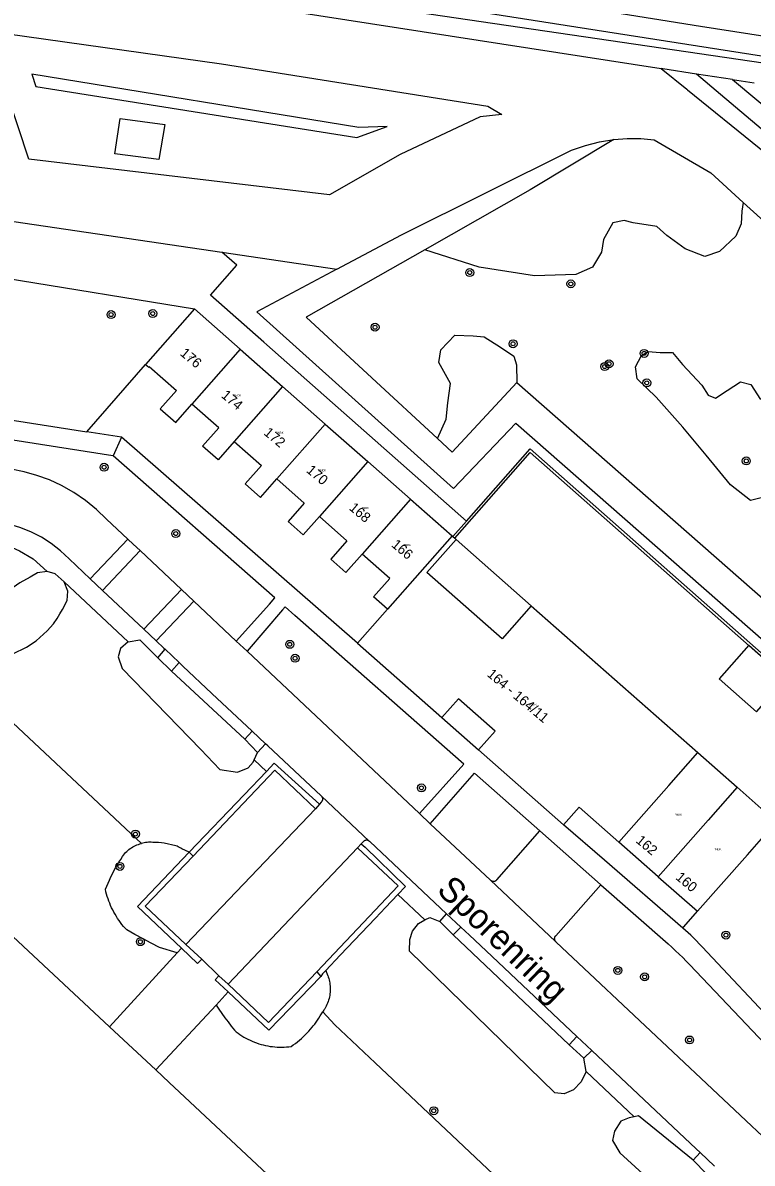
# Model space of a CAD drawing. Extents: x 132994 to 136000, y 393499 to 395512.
# Drawn here: x 133162.3 to 133235.6, y 394136.6 to 394251.1 of the extents above; entities that cross this region are included whole.
import ezdxf

# ---------------------------------------------------------------- set-up
doc = ezdxf.new("R2010")
doc.units = 0
for name, color, linetype in [('gg-anno-huisnummerreeks BGT', 7, 'Continuous'), ('gg-anno-openbare ruimte label', 7, 'Continuous'), ('gg-knt-bronhoudergrens niveau 01', 7, 'Continuous'), ('gg-kntw-bovenkant insteek waterloop', 7, 'Continuous'), ('gt-symb-boom', 7, 'Continuous'), ('gx-grn-maaiveld', 7, 'Continuous'), ('kenmerkpunt-x pandkandidaat', 7, 'Continuous')]:
    doc.layers.add(name, color=color, linetype=linetype)

# ---------------------------------------------------------------- blocks, each defined once
blk = doc.blocks.new('gt0-BOOM')
at = {"layer": 'gt-symb-boom'}
for radius in [0.4, 0.2]:
    blk.add_circle((0, 0), radius, dxfattribs=at)

msp = doc.modelspace()

# ---------------------------------------------------------------- linework, layer by layer
at = {"layer": 'gg-knt-bronhoudergrens niveau 01'}
msp.add_lwpolyline([(133235.24, 394188.61), (133232.26, 394185.23), (133236.01, 394181.93), (133238.99, 394185.3), (133235.24, 394188.61)], dxfattribs=at)
at = {"layer": 'gg-kntw-bovenkant insteek waterloop'}
msp.add_lwpolyline([(133000, 394279.68), (133030.54, 394275.9), (133128.46, 394261.71), (133226.43, 394246.51)], dxfattribs=at)
at = {"layer": 'gx-grn-maaiveld'}
for p, q in [((133226.6, 394246.48), (133226.43, 394246.51)), ((133229.99, 394245.96), (133226.6, 394246.48)), ((133233.58, 394245.41), (133229.99, 394245.96)), ((133233.58, 394245.41), (133235.77, 394245.07)), ((133234.68, 394233.07), (133242.31, 394226.14)), ((133161.43, 394231.16), (133182.33, 394228.07)), ((133182.33, 394228.07), (133193.87, 394226.36)), ((133160.66, 394225.47), (133179.57, 394222.38)), ((133179.57, 394222.38), (133174.66, 394216.8)), ((133179.57, 394222.38), (133184.17, 394218.33)), ((133184.17, 394218.33), (133179.31, 394212.82)), ((133184.17, 394218.33), (133188.42, 394214.59)), ((133168.77, 394210.04), (133174.66, 394216.8)), ((133188.42, 394214.59), (133183.56, 394209.08)), ((133188.42, 394214.59), (133192.69, 394210.82)), ((133158.67, 394211.61), (133168.77, 394210.04)), ((133192.69, 394210.82), (133187.84, 394205.31)), ((133192.69, 394210.82), (133196.97, 394207.05)), ((133172.24, 394209.5), (133168.77, 394210.04)), ((133172.24, 394209.5), (133171.41, 394207.63)), ((133196.97, 394207.05), (133192.12, 394201.54)), ((133196.97, 394207.05), (133201.26, 394203.27)), ((133201.26, 394203.27), (133196.41, 394197.76)), ((133201.26, 394203.27), (133205.43, 394199.59)), ((133205.51, 394199.52), (133206.88, 394201.08)), ((133205.43, 394199.59), (133198.95, 394192.24)), ((133205.51, 394199.52), (133205.43, 394199.59)), ((133205.51, 394199.52), (133205.7, 394199.36)), ((133205.7, 394199.36), (133205.83, 394199.24)), ((133172.88, 394199.27), (133169.1, 394195.29)), ((133213.39, 394192.58), (133205.83, 394199.24)), ((133174.1, 394198.12), (133170.33, 394194.13)), ((133174.1, 394198.12), (133178.26, 394194.21)), ((133166.48, 394195), (133172.92, 394188.96)), ((133170.33, 394194.13), (133169.1, 394195.29)), ((133174.48, 394190.22), (133170.33, 394194.13)), ((133178.26, 394194.21), (133174.48, 394190.22)), ((133178.26, 394194.21), (133179.5, 394193.04)), ((133179.5, 394193.04), (133175.71, 394189.05)), ((133179.5, 394193.04), (133183.76, 394189.03)), ((133213.39, 394192.58), (133230.11, 394177.85)), ((133198.95, 394192.24), (133195.94, 394188.83)), ((133175.71, 394189.05), (133174.48, 394190.22)), ((133183.76, 394189.03), (133184.85, 394188.02)), ((133175.87, 394187.34), (133176.61, 394188.21)), ((133176.61, 394188.21), (133178.02, 394186.88)), ((133202.17, 394171.72), (133184.85, 394188.02)), ((133195.94, 394188.83), (133204.42, 394181.36)), ((133175.87, 394187.34), (133177.25, 394186.01)), ((133178.02, 394186.88), (133177.25, 394186.01)), ((133177.25, 394186.01), (133184.61, 394179.18)), ((133204.42, 394181.36), (133208.1, 394178.11)), ((133184.61, 394179.18), (133185.36, 394179.99)), ((133185.36, 394179.99), (133186.71, 394178.72)), ((133184.61, 394179.18), (133185.9, 394177.86)), ((133185.9, 394177.86), (133186.71, 394178.72)), ((133185.56, 394177.12), (133185.9, 394177.86)), ((133208.1, 394178.11), (133216.63, 394170.6)), ((133230.11, 394177.85), (133234.06, 394174.37)), ((133186.79, 394175.96), (133185.56, 394177.12)), ((133234.06, 394174.37), (133231.15, 394171.07)), ((133234.06, 394174.37), (133237.99, 394170.9)), ((133192.32, 394173.47), (133197.12, 394168.96)), ((133191.71, 394172.21), (133178.71, 394158.57)), ((133192.12, 394172.68), (133191.71, 394172.21)), ((133216.63, 394170.6), (133218.19, 394172.38)), ((133218.19, 394172.38), (133222.19, 394168.86)), ((133203.24, 394170.7), (133202.17, 394171.72)), ((133209.3, 394165.04), (133203.24, 394170.7)), ((133231.15, 394171.07), (133226.14, 394165.38)), ((133235.09, 394167.59), (133237.9, 394170.79)), ((133196.31, 394168.68), (133195.94, 394168.29)), ((133226.14, 394165.38), (133222.19, 394168.86)), ((133179.04, 394167.85), (133179.45, 394167.44)), ((133195.94, 394168.29), (133182.94, 394154.6)), ((133235.09, 394167.59), (133230.09, 394161.91)), ((133215.83, 394158.89), (133209.3, 394165.04)), ((133226.14, 394165.38), (133230.09, 394161.91)), ((133202.7, 394161.04), (133199.99, 394163.59)), ((133204.19, 394160.9), (133204.89, 394161.66)), ((133204.89, 394161.66), (133206.3, 394160.33)), ((133204.19, 394160.9), (133205.56, 394159.55)), ((133205.56, 394159.55), (133206.3, 394160.33)), ((133217.19, 394148.52), (133205.56, 394159.55)), ((133178.25, 394158.2), (133177.82, 394157.73)), ((133180.29, 394157.1), (133178.71, 394158.57)), ((133177.82, 394157.73), (133171.04, 394150.32)), ((133182.02, 394155.44), (133180.29, 394157.1)), ((133191.86, 394155.83), (133192.26, 394155.38)), ((133182.02, 394155.44), (133182.94, 394154.6)), ((133181.73, 394152.5), (133182.94, 394153.81)), ((133175.67, 394146), (133181.73, 394152.5)), ((133171.04, 394150.32), (133175.67, 394146)), ((133217.19, 394148.52), (133217.96, 394149.35)), ((133217.96, 394149.35), (133219.46, 394147.93)), ((133218.67, 394147.16), (133217.19, 394148.52)), ((133218.67, 394147.16), (133219.46, 394147.93)), ((133218.9, 394145.82), (133218.67, 394147.16)), ((133223.73, 394141.27), (133218.9, 394145.82)), ((133229.63, 394136.92), (133230.35, 394137.69)), ((133231.79, 394136.33), (133230.35, 394137.69)), ((133230.97, 394135.56), (133229.63, 394136.92))]:
    msp.add_line(p, q, dxfattribs=at)
for points in [[(133000, 394283.61), (133006.65, 394282.79), (133009.42, 394282.22), (133051.12, 394276.6), (133083.16, 394271.78), (133137.1, 394263.26), (133176.74, 394257.15), (133239.73, 394247.29), (133319.89, 394234.75), (133367.61, 394227.28), (133367.8, 394227.24), (133367.58, 394225.98), (133367.42, 394226.01), (133357.3, 394227.92), (133315.33, 394234.59), (133277.4, 394240.61), (133240.55, 394246.47), (133201.95, 394252.14), (133139.43, 394262.02), (133051.35, 394275.59), (133009.25, 394281.47), (133006.61, 394281.68), (133000, 394282.47)], [(133098.44, 394271.62), (133113.79, 394269.24), (133135.01, 394266.02), (133154.52, 394262.95), (133175.04, 394259.64), (133230.39, 394250.78), (133249.11, 394247.87), (133285.7, 394242.17), (133296.88, 394240.16), (133304.19, 394238.9), (133314.3, 394237.48), (133330.27, 394234.8), (133344.79, 394232.54), (133356.53, 394230.63), (133366.93, 394228.78), (133367.87, 394228.47), (133368.26, 394228.41)], [(133210.42, 394241.91), (133208.26, 394241.65), (133200.23, 394237.9), (133193.12, 394233.82), (133162.94, 394237.41), (133158.65, 394250.29), (133182.29, 394247), (133209.04, 394242.72), (133210.42, 394241.91)], [(133226.43, 394246.51), (133229, 394244.43), (133229.08, 394244.36), (133265.07, 394215.25), (133306.28, 394180.76), (133352.39, 394141.8), (133354.6, 394144.57), (133354.68, 394144.68), (133354.87, 394144.91)], [(133195.88, 394239.59), (133198.93, 394240.7), (133196.07, 394240.58), (133163.23, 394245.96), (133163.65, 394244.72), (133195.88, 394239.59)], [(133233.58, 394245.41), (133236.03, 394243.38), (133247.17, 394234.15), (133309.55, 394182.31), (133353.84, 394145.2), (133354.03, 394144.51), (133353.24, 394143.57), (133352.46, 394143.64), (133308.58, 394180.49), (133245.9, 394232.5), (133232.4, 394243.92), (133229.99, 394245.96)], [(133171.57, 394237.95), (133172.12, 394241.51), (133176.58, 394240.88), (133175.98, 394237.38), (133171.57, 394237.95)], [(133193.87, 394226.36), (133200.37, 394229.81), (133217.44, 394238.32), (133218.82, 394238.8), (133220.24, 394239.17), (133221.68, 394239.4)], [(133221.68, 394239.4), (133213.27, 394234.34), (133202.7, 394228.32)], [(133221.68, 394239.4), (133223.03, 394239.5), (133224.38, 394239.49), (133225.72, 394239.37), (133231.41, 394236.04), (133234.68, 394233.07)], [(133234.68, 394233.07), (133234.54, 394232.2), (133234.47, 394230.94), (133233.94, 394229.68), (133232.29, 394228.16), (133230.83, 394227.63), (133228.85, 394228.43), (133226.99, 394229.75), (133226, 394230.67), (133223.62, 394231.01), (133222.7, 394231.27), (133221.57, 394231.01), (133220.65, 394229.35), (133220.45, 394228.09), (133219.52, 394226.57), (133217.87, 394225.85), (133213.7, 394225.71), (133208.14, 394226.57), (133202.7, 394228.32)], [(133206.88, 394201.08), (133186.83, 394218.78), (133186.54, 394219.03), (133181.18, 394223.76), (133183.81, 394226.77), (133182.33, 394228.07)], [(133202.7, 394228.32), (133190.78, 394221.54), (133203.97, 394209.38)], [(133193.87, 394226.36), (133185.83, 394222.1), (133205.59, 394204.34), (133211.84, 394210.9), (133241.65, 394184.75)], [(133203.97, 394209.38), (133204.85, 394211.33), (133205.01, 394212.97), (133205.27, 394214.88), (133204.11, 394216.99), (133204.32, 394218.26), (133205.7, 394219.74), (133207.55, 394219.69), (133208.66, 394219.59), (133210.3, 394218.53), (133211.62, 394217.63), (133211.89, 394216.78), (133211.95, 394215)], [(133236.62, 394203.46), (133235.4, 394203.14), (133233.39, 394204.73), (133230.95, 394207.69), (133228.62, 394210.5), (133225.93, 394213.51), (133224.02, 394215.36), (133223.86, 394216.58), (133224.44, 394217.69), (133225.13, 394218.12), (133226.32, 394218), (133227.57, 394218.01)], [(133227.57, 394218.01), (133228.57, 394216.79), (133230.53, 394214.73), (133231.16, 394213.73), (133231.9, 394213.41), (133233.07, 394214.2), (133234.39, 394215.05), (133235.45, 394214.78), (133236.4, 394213.3)], [(133174.66, 394216.8), (133174.97, 394216.53), (133175.03, 394216.59), (133177.75, 394214.19), (133176.13, 394212.34), (133177.68, 394210.97), (133179.31, 394212.82)], [(133203.97, 394209.38), (133205.46, 394208), (133211.95, 394215)], [(133211.95, 394215), (133239.7, 394190.62), (133247.08, 394214.42)], [(133183.56, 394209.08), (133181.93, 394207.23), (133180.38, 394208.6), (133182.01, 394210.44), (133179.31, 394212.82)], [(133171.41, 394207.63), (133171.38, 394207.65), (133146.13, 394211.57)], [(133172.88, 394199.27), (133170.74, 394201.28), (133169.72, 394202.26), (133168.61, 394203.15), (133167.44, 394203.94), (133166.21, 394204.64), (133165, 394205.21), (133163.75, 394205.67), (133162.48, 394206.04), (133161.17, 394206.31), (133153.53, 394207.51), (133145.71, 394208.73)], [(133195.94, 394188.83), (133172.25, 394209.5), (133172.24, 394209.5)], [(133183.56, 394209.08), (133186.3, 394206.67), (133184.67, 394204.82), (133186.21, 394203.46), (133187.84, 394205.31)], [(133000, 394207.62), (133011.63, 394205.79), (133088.29, 394193.88), (133091.71, 394193.32), (133108.3, 394194.35), (133112.46, 394190.02), (133131.72, 394186.98), (133171.04, 394150.32)], [(133183.76, 394189.03), (133187.09, 394192.74), (133187.65, 394193.37), (133171.41, 394207.63)], [(133205.7, 394199.36), (133213.28, 394207.97), (133245.86, 394179.24), (133238.28, 394170.65)], [(133206.88, 394201.08), (133213.26, 394208.32), (133246.21, 394179.27), (133239.72, 394171.91)], [(133187.84, 394205.31), (133190.59, 394202.88), (133188.97, 394201.04), (133190.49, 394199.69), (133192.12, 394201.54)], [(133169.1, 394195.29), (133166.97, 394197.3), (133166.12, 394198.11), (133165.19, 394198.83), (133164.19, 394199.47), (133163.14, 394200.01), (133162.04, 394200.45), (133160.91, 394200.79), (133146.06, 394203.12), (133146.01, 394203.13)], [(133192.12, 394201.54), (133194.88, 394199.11), (133193.25, 394197.26), (133194.78, 394195.91), (133196.41, 394197.76)], [(133151.35, 394200.21), (133160.45, 394198.79), (133161.98, 394198.1), (133163.36, 394197.28), (133164.79, 394196.01)], [(133172.88, 394199.27), (133173.42, 394198.75), (133174.1, 394198.12)], [(133213.39, 394192.58), (133210.47, 394189.26), (133202.91, 394195.92), (133205.83, 394199.24)], [(133198.95, 394192.24), (133197.55, 394193.48), (133199.17, 394195.33), (133196.41, 394197.76)], [(133164.79, 394196.01), (133163.81, 394195.89), (133163.06, 394195.45), (133162.02, 394194.88), (133160.93, 394194.1), (133160.7, 394193.93), (133160.08, 394193.37), (133159.32, 394192.8), (133158.39, 394191.59), (133158.01, 394190.62), (133157.85, 394189.43), (133158.45, 394188.52), (133159.88, 394187.74), (133161.31, 394187.76), (133162.7, 394188.41), (133163.67, 394189.07), (133164.78, 394190.07), (133165.4, 394190.76), (133165.77, 394191.31), (133166.06, 394191.78), (133166.3, 394192.21), (133166.79, 394193.11), (133166.85, 394194.05), (133166.48, 394195)], [(133166.48, 394195), (133165.59, 394195.78), (133164.79, 394196.01)], [(133202.17, 394171.72), (133206.63, 394176.69), (133189.64, 394191.62), (133188.68, 394192.47), (133188.41, 394192.16), (133184.85, 394188.02)], [(133172.92, 394188.96), (133174.08, 394189.15), (133175.87, 394187.34)], [(133175.71, 394189.05), (133176.49, 394188.33), (133176.61, 394188.21)], [(133174.23, 394168.72), (133156.99, 394184.89), (133155.85, 394185.96), (133153.39, 394188.27)], [(133172.92, 394188.96), (133172.15, 394188.3), (133171.91, 394187.46), (133172.32, 394186.27), (133180.2, 394178.14), (133182.11, 394176.14), (133183.9, 394175.88), (133184.95, 394176.31), (133185.45, 394176.88), (133185.56, 394177.12)], [(133178.02, 394186.88), (133178.39, 394186.53), (133181.32, 394183.77), (133185.36, 394179.99)], [(133208.1, 394178.11), (133209.77, 394180), (133206.09, 394183.25), (133204.42, 394181.36)], [(133192.32, 394173.47), (133192.29, 394173.49), (133186.92, 394178.53), (133186.71, 394178.72)], [(133222.19, 394168.86), (133227.2, 394174.55), (133230.11, 394177.85)], [(133192.12, 394172.68), (133187.57, 394176.78), (133186.79, 394175.96)], [(133186.79, 394175.96), (133184.54, 394173.6), (133179.04, 394167.85)], [(133179.45, 394167.44), (133187.65, 394176.07), (133191.71, 394172.21)], [(133203.24, 394170.7), (133207.67, 394175.79), (133214.24, 394169.98)], [(133192.32, 394173.47), (133192.34, 394173.44), (133192.36, 394173.41), (133192.38, 394173.38), (133192.39, 394173.35), (133192.41, 394173.31), (133192.42, 394173.28), (133192.42, 394173.24), (133192.43, 394173.21), (133192.43, 394173.17), (133192.43, 394173.13), (133192.42, 394173.1), (133192.41, 394173.06), (133192.4, 394173.03), (133192.39, 394173), (133192.37, 394172.97), (133192.35, 394172.94), (133192.33, 394172.91), (133192.3, 394172.88), (133192.12, 394172.68)], [(133209.3, 394165.04), (133209.33, 394165.01), (133209.36, 394164.99), (133209.4, 394164.97), (133209.43, 394164.96), (133209.47, 394164.95), (133209.51, 394164.94), (133209.55, 394164.93), (133209.59, 394164.93), (133209.63, 394164.93), (133209.67, 394164.93), (133209.71, 394164.94), (133209.75, 394164.95), (133209.79, 394164.97), (133209.83, 394164.99), (133209.86, 394165.01), (133209.89, 394165.03), (133209.93, 394165.06), (133214.24, 394169.98)], [(133214.24, 394169.98), (133220.35, 394164.6), (133220.37, 394164.58)], [(133228.6, 394160.21), (133220.74, 394167.04), (133216.63, 394170.6)], [(133177.82, 394157.73), (133176.06, 394158.28), (133175.23, 394158.72), (133174.41, 394159.15), (133173.58, 394159.59), (133172.76, 394160.04), (133172.6, 394160.22), (133172.44, 394160.4), (133172.28, 394160.59), (133172.13, 394160.79), (133171.99, 394160.99), (133171.85, 394161.19), (133171.72, 394161.4), (133171.59, 394161.61), (133171.47, 394161.82), (133171.36, 394162.04), (133171.25, 394162.26), (133171.15, 394162.49), (133171.05, 394162.71), (133170.97, 394162.94), (133170.89, 394163.17), (133170.81, 394163.41), (133170.74, 394163.64), (133170.68, 394163.88), (133170.63, 394164.12), (133170.75, 394164.43), (133170.89, 394164.75), (133171.02, 394165.05), (133171.17, 394165.36), (133171.32, 394165.66), (133171.47, 394165.96), (133171.64, 394166.26), (133171.8, 394166.55), (133171.98, 394166.84), (133172.16, 394167.12), (133172.35, 394167.41), (133172.54, 394167.68), (133172.65, 394167.8), (133172.76, 394167.91), (133172.87, 394168.01), (133172.99, 394168.11), (133173.11, 394168.2), (133173.24, 394168.29), (133173.37, 394168.37), (133173.51, 394168.44), (133173.65, 394168.51), (133173.79, 394168.57), (133173.93, 394168.63), (133174.08, 394168.68), (133174.23, 394168.72)], [(133179.04, 394167.85), (133178.3, 394168.19), (133178.18, 394168.26), (133178.06, 394168.33), (133177.94, 394168.39), (133177.82, 394168.44), (133177.69, 394168.49), (133176.52, 394168.74), (133176.24, 394168.77), (133175.95, 394168.8), (133175.66, 394168.82), (133175.37, 394168.83), (133175.23, 394168.84), (133175.09, 394168.84), (133174.95, 394168.84), (133174.8, 394168.83), (133174.66, 394168.81), (133174.52, 394168.79), (133174.38, 394168.76), (133174.24, 394168.73), (133174.23, 394168.72)], [(133197.12, 394168.96), (133197.08, 394168.98), (133197.05, 394169), (133197.01, 394169.02), (133196.98, 394169.03), (133196.93, 394169.04), (133196.9, 394169.05), (133196.86, 394169.05), (133196.82, 394169.05), (133196.78, 394169.04), (133196.74, 394169.03), (133196.7, 394169.02), (133196.66, 394169.01), (133196.63, 394168.99), (133196.59, 394168.97), (133196.56, 394168.94), (133196.53, 394168.91), (133196.31, 394168.68)], [(133196.31, 394168.68), (133196.7, 394168.36), (133200.77, 394164.4), (133199.99, 394163.59)], [(133204.89, 394161.66), (133197.17, 394168.92), (133197.15, 394168.93), (133197.12, 394168.96)], [(133178.25, 394158.2), (133173.85, 394162.38), (133179.04, 394167.85)], [(133179.45, 394167.44), (133174.62, 394162.43), (133178.71, 394158.57)], [(133195.94, 394168.29), (133200.01, 394164.45), (133191.86, 394155.83)], [(133215.83, 394158.89), (133215.81, 394158.92), (133215.79, 394158.95), (133215.77, 394158.98), (133215.76, 394159.01), (133215.75, 394159.04), (133215.74, 394159.08), (133215.74, 394159.11), (133215.73, 394159.15), (133215.73, 394159.19), (133215.74, 394159.23), (133215.74, 394159.26), (133215.76, 394159.3), (133215.77, 394159.33), (133215.79, 394159.37), (133215.8, 394159.4), (133215.83, 394159.43), (133215.85, 394159.46), (133220.37, 394164.58)], [(133220.37, 394164.58), (133227.14, 394158.64), (133227.51, 394158.3), (133227.88, 394157.95), (133228.24, 394157.61), (133228.6, 394157.26), (133228.95, 394156.91), (133229.3, 394156.55), (133243.77, 394141.31)], [(133199.99, 394163.59), (133198.75, 394162.28), (133197.75, 394161.22), (133194.21, 394157.5), (133192.76, 394155.97)], [(133228.6, 394160.21), (133228.72, 394160.35), (133230.09, 394161.91)], [(133218.9, 394145.82), (133218.4, 394144.8), (133217.62, 394143.98), (133216.68, 394143.57), (133215.75, 394143.69), (133201.16, 394157.91), (133201.19, 394159.07), (133201.45, 394159.92), (133202.05, 394160.7), (133202.7, 394161.04)], [(133202.7, 394161.04), (133203.2, 394161.3), (133204.19, 394160.9)], [(133206.3, 394160.33), (133207.17, 394159.51), (133208.85, 394157.93), (133217.96, 394149.35)], [(133238.36, 394150.06), (133230.54, 394158.33), (133230.26, 394158.65), (133229.97, 394158.96), (133229.67, 394159.26), (133229.41, 394159.5), (133229.14, 394159.74), (133228.86, 394159.98), (133228.6, 394160.21)], [(133180.29, 394157.1), (133179.87, 394156.66), (133178.25, 394158.2)], [(133238.91, 394137.15), (133238.88, 394137.18), (133226.5, 394148.85), (133215.9, 394158.82), (133215.88, 394158.84), (133215.85, 394158.86), (133215.83, 394158.89)], [(133191.86, 394155.83), (133187.01, 394150.73), (133182.94, 394154.6)], [(133192.76, 394155.97), (133192.43, 394155.62), (133192.26, 394155.38)], [(133192.76, 394155.97), (133192.94, 394155.5), (133192.95, 394155.47), (133193, 394155.32), (133193.05, 394155.17), (133193.09, 394155.02), (133193.12, 394154.87), (133193.15, 394154.72), (133193.17, 394154.57), (133193.19, 394154.41), (133193.2, 394154.26), (133193.2, 394154.1), (133193.2, 394153.94), (133193.19, 394153.78), (133193.17, 394153.62), (133193.15, 394153.46), (133193.12, 394153.31), (133193.08, 394153.15), (133193.04, 394152.99), (133192.99, 394152.84), (133192.93, 394152.69), (133192.87, 394152.54), (133192.8, 394152.4), (133192.73, 394152.26), (133192.65, 394152.12), (133192.6, 394152.04), (133192.55, 394151.97), (133192.5, 394151.89), (133192.44, 394151.82)], [(133182.94, 394153.81), (133181.65, 394155.02), (133182.02, 394155.44)], [(133182.94, 394153.81), (133187.02, 394149.99), (133192.26, 394155.38)], [(133181.73, 394152.5), (133182.02, 394152.07), (133182.33, 394151.65), (133182.63, 394151.22), (133182.94, 394150.8), (133183.26, 394150.39), (133183.57, 394149.97), (133183.76, 394149.82), (133183.94, 394149.68), (133184.13, 394149.55), (133184.33, 394149.42), (133184.53, 394149.29), (133184.73, 394149.18), (133184.94, 394149.07), (133185.15, 394148.96), (133185.37, 394148.87), (133185.58, 394148.78), (133185.8, 394148.69), (133186.02, 394148.62), (133186.25, 394148.55), (133186.48, 394148.49), (133186.71, 394148.44), (133186.93, 394148.39), (133187.17, 394148.35), (133187.4, 394148.32), (133187.63, 394148.3), (133187.87, 394148.28), (133188.1, 394148.27), (133188.34, 394148.27), (133188.57, 394148.28), (133188.8, 394148.29), (133189.04, 394148.31), (133189.27, 394148.34), (133189.49, 394148.49), (133189.7, 394148.65), (133189.91, 394148.81), (133190.11, 394148.98), (133190.31, 394149.15), (133190.5, 394149.33), (133190.69, 394149.51), (133190.88, 394149.7), (133191.06, 394149.89), (133191.23, 394150.09), (133191.4, 394150.29), (133191.49, 394150.4), (133191.64, 394150.59), (133191.78, 394150.79), (133191.93, 394150.99), (133192.06, 394151.19), (133192.2, 394151.4), (133192.32, 394151.61), (133192.44, 394151.82)], [(133192.44, 394151.82), (133193.67, 394150.52), (133195.95, 394148.37), (133196.02, 394148.3), (133197.71, 394146.71), (133230.91, 394115.37), (133232.14, 394114.21)], [(133230.35, 394137.69), (133229.96, 394138.05), (133219.46, 394147.93)], [(133175.67, 394146), (133177.02, 394144.73), (133287.89, 394041.06)], [(133223.73, 394141.27), (133223.21, 394141.16), (133222.39, 394140.84), (133221.74, 394139.85), (133221.54, 394138.91), (133222.29, 394137.66), (133240.33, 394121.2), (133241.44, 394121.1), (133242.49, 394121.72), (133243.41, 394122.76)], [(133229.63, 394136.92), (133224.16, 394141.36), (133223.73, 394141.27)]]:
    msp.add_lwpolyline(points, dxfattribs=at)

# ---------------------------------------------------------------- block references
at = {"layer": 'gt-symb-boom'}
for p in [(133207.21, 394226.03), (133217.36, 394224.9), (133175.38, 394221.92), (133171.19, 394221.81), (133197.7, 394220.55), (133211.56, 394218.88), (133224.72, 394217.92), (133220.76, 394216.6), (133221.2, 394216.87), (133224.99, 394214.96), (133234.98, 394207.12), (133170.49, 394206.49), (133177.69, 394199.83), (133189.14, 394188.71), (133189.67, 394187.31), (133202.36, 394174.3), (133173.64, 394169.66), (133172.08, 394166.42), (133174.13, 394158.86), (133232.94, 394159.52), (133222.08, 394155.98), (133224.77, 394155.33), (133229.28, 394148.99), (133203.6, 394141.89)]:
    msp.add_blockref('gt0-BOOM', p, dxfattribs=at)

# ---------------------------------------------------------------- texts
at = {"layer": 'gg-anno-huisnummerreeks BGT'}
for s, p in [('176', (133178.05, 394217.8)), ('174', (133182.18, 394213.58)), ('172', (133186.45, 394209.83)), ('170', (133190.73, 394206.06)), ('168', (133195.02, 394202.29)), ('166', (133199.27, 394198.59)), ('164 - 164/11', (133208.87, 394185.59)), ('162', (133223.82, 394168.89)), ('160', (133227.81, 394165.2))]:
    msp.add_text(s, height=1, rotation=320, dxfattribs=at).set_placement(p)
at = {"layer": 'gg-anno-openbare ruimte label'}
msp.add_text('Sporenring', height=2.5, rotation=316.1, dxfattribs=at).set_placement((133203.79, 394163.91))
at = {"layer": 'kenmerkpunt-x pandkandidaat'}
for p in [(133179.04, 394217.47), (133183.49, 394213.6), (133187.75, 394209.85), (133192.03, 394206.08), (133196.32, 394202.3), (133200.55, 394198.58), (133213.18, 394182.54), (133227.75, 394171.52), (133231.7, 394168.04)]:
    msp.add_text('PNDK', height=0.2, dxfattribs=at).set_placement(p)

doc.saveas('drawing.dxf')
